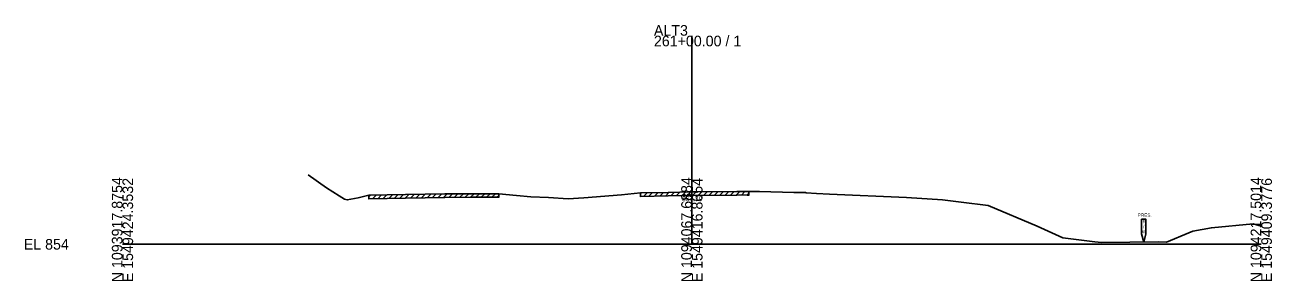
# Model space of a CAD drawing. Extents: x -26 to 1303, y -10 to 19582.
# Drawn here: x 974.3 to 1302.8, y 14490.3 to 14557.8 of the extents above; entities that cross this region are included whole.
import ezdxf

# ---------------------------------------------------------------- set-up
doc = ezdxf.new("R2010")
doc.units = 0
for name, color, linetype in [('Default', 7, 'Continuous'), ('RD_GPK_XS_Cell', 7, 'Continuous'), ('RD_XS_ExGround', 7, 'Continuous'), ('RD_XS_ExPaveRet', 7, 'Continuous'), ('RD_XS_ExRW', 7, 'Continuous'), ('RD_XS_TX_Elev_EX', 7, 'Continuous')]:
    doc.layers.add(name, color=color, linetype=linetype)

msp = doc.modelspace()

# ---------------------------------------------------------------- linework, layer by layer
at = {"layer": 'RD_GPK_XS_Cell'}
for p, q in [((1150, 14500), (1150, 14554.97)), ((1000, 14500), (1150, 14500)), ((1150, 14500), (1300, 14500))]:
    msp.add_line(p, q, dxfattribs=at)
at = {"layer": 'RD_XS_ExGround'}
msp.add_lwpolyline([(1048.93, 14518.32), (1053.72, 14514.89), (1057.12, 14512.73), (1058.5, 14511.93), (1059.22, 14511.71), (1062.13, 14512.27), (1064.92, 14512.93), (1074.6, 14513.09), (1084.91, 14513.32), (1092.09, 14513.33), (1099.15, 14513.33), (1103.81, 14512.82), (1107.54, 14512.49), (1112.23, 14512.3), (1117.37, 14512.01), (1121.56, 14512.2), (1131.43, 14513.03), (1136.48, 14513.54), (1143.79, 14513.69), (1149.89, 14513.79), (1161.88, 14513.91), (1163.31, 14513.94), (1164.54, 14513.9), (1164.98, 14513.88), (1165.18, 14513.94), (1165.38, 14513.92), (1166.16, 14513.91), (1166.59, 14513.9), (1167.85, 14513.87), (1176.82, 14513.69), (1177.74, 14513.65), (1179.78, 14513.61), (1179.97, 14513.61), (1180.14, 14513.52), (1182.8, 14513.4), (1186.29, 14513.22), (1206.55, 14512.31), (1216.05, 14511.71), (1220.94, 14511.11), (1228.04, 14510.24), (1241, 14504.76), (1247.74, 14501.73), (1256.12, 14500.66), (1257.91, 14500.5), (1272.8, 14500.63), (1275.03, 14500.57), (1280.93, 14503.03), (1282.01, 14503.49), (1286.87, 14504.36), (1297.89, 14505.41), (1300, 14504.76)], dxfattribs=at)
at = {"layer": 'RD_XS_ExPaveRet'}
for p, q in [((1064.92, 14512.49), (1065.36, 14512.94)), ((1064.92, 14512.93), (1064.92, 14511.93)), ((1065.83, 14512), (1066.8, 14512.96)), ((1067.27, 14512.02), (1068.24, 14512.99)), ((1068.71, 14512.04), (1069.68, 14513.01)), ((1070.15, 14512.07), (1071.12, 14513.03)), ((1071.59, 14512.09), (1072.55, 14513.06)), ((1073.03, 14512.12), (1073.99, 14513.08)), ((1074.46, 14512.14), (1075.44, 14513.11)), ((1075.91, 14512.17), (1076.88, 14513.14)), ((1077.36, 14512.2), (1078.33, 14513.18)), ((1078.8, 14512.24), (1079.77, 14513.21)), ((1080.25, 14512.27), (1081.22, 14513.24)), ((1081.7, 14512.3), (1082.67, 14513.27)), ((1083.14, 14512.33), (1084.11, 14513.3)), ((1084.59, 14512.36), (1085.55, 14513.32)), ((1086.01, 14512.37), (1086.96, 14513.33)), ((1087.43, 14512.38), (1088.38, 14513.33)), ((1088.84, 14512.38), (1089.8, 14513.33)), ((1090.26, 14512.38), (1091.21, 14513.33)), ((1091.68, 14512.38), (1092.63, 14513.33)), ((1093.09, 14512.38), (1094.04, 14513.33)), ((1094.5, 14512.38), (1095.45, 14513.33)), ((1095.92, 14512.38), (1096.87, 14513.33)), ((1097.33, 14512.38), (1098.28, 14513.33)), ((1098.74, 14512.38), (1099.15, 14512.79)), ((1099.15, 14513.33), (1099.15, 14512.33)), ((1136.48, 14513.27), (1136.76, 14513.55)), ((1136.48, 14513.54), (1136.48, 14512.54)), ((1137.23, 14512.61), (1138.2, 14513.58)), ((1138.68, 14512.64), (1139.65, 14513.61)), ((1140.12, 14512.67), (1141.09, 14513.64)), ((1141.56, 14512.7), (1142.53, 14513.67)), ((1143.01, 14512.72), (1143.97, 14513.69)), ((1144.45, 14512.75), (1145.41, 14513.72)), ((1145.88, 14512.77), (1146.85, 14513.74)), ((1147.32, 14512.8), (1148.29, 14513.76)), ((1148.76, 14512.82), (1149.72, 14513.79)), ((1150.19, 14512.84), (1151.15, 14513.8)), ((1151.62, 14512.86), (1152.58, 14513.82)), ((1153.05, 14512.87), (1154.01, 14513.83)), ((1154.48, 14512.89), (1155.44, 14513.85)), ((1155.91, 14512.9), (1156.87, 14513.86)), ((1157.34, 14512.92), (1158.3, 14513.88)), ((1158.77, 14512.93), (1159.73, 14513.89)), ((1160.2, 14512.95), (1161.16, 14513.91)), ((1161.63, 14512.96), (1162.59, 14513.93)), ((1163.06, 14512.98), (1163.99, 14513.91)), ((1164.44, 14512.95), (1164.98, 14513.48)), ((1164.98, 14513.88), (1164.98, 14512.88))]:
    msp.add_line(p, q, dxfattribs=at)
for points in [[(1064.92, 14511.98), (1074.6, 14512.14), (1084.91, 14512.37), (1092.09, 14512.38), (1099.15, 14512.38)], [(1136.48, 14512.59), (1143.79, 14512.74), (1149.89, 14512.84), (1161.88, 14512.96), (1163.31, 14512.99), (1164.54, 14512.95), (1164.98, 14512.93)]]:
    msp.add_lwpolyline(points, dxfattribs=at)
at = {"layer": 'RD_XS_ExRW'}
msp.add_lwpolyline([(1268.49, 14506.61), (1269.59, 14506.61), (1269.59, 14502.78), (1269.04, 14500.59), (1268.49, 14502.78)], close=True, dxfattribs=at)

# ---------------------------------------------------------------- texts
at = {"layer": 'Default'}
msp.add_text('-', height=0.0001, dxfattribs=at).set_placement((1000, 14500))
at = {"layer": 'RD_GPK_XS_Cell'}
for s, p in [('ALT3', (1140, 14554.97)), ('261+00.00 / 1', (1140, 14552.17)), ('EL 854', (974, 14498.6))]:
    msp.add_text(s, height=2.8, dxfattribs=at).set_placement(p)
for s, p in [('N 1093917.8754', (1000, 14490)), ('E 1549424.3532', (1002.8, 14490)), ('N 1094067.6884', (1150, 14490)), ('E 1549416.8654', (1152.8, 14490)), ('N 1094217.5014', (1300, 14490)), ('E 1549409.3776', (1302.8, 14490))]:
    msp.add_text(s, height=2.8, rotation=90, dxfattribs=at).set_placement(p)
at = {"layer": 'RD_XS_ExRW'}
for s, p in [('PRES.', (1267.5, 14507.24)), ('R', (1268.76, 14505.52)), ('/', (1268.88, 14504.21)), ('W', (1268.57, 14502.89))]:
    msp.add_text(s, height=0.875, dxfattribs=at).set_placement(p)
at = {"layer": 'RD_XS_TX_Elev_EX'}
msp.add_text('867.79', height=1.25, dxfattribs=at).set_placement((1147.44, 14511.36))

doc.saveas('drawing.dxf')
